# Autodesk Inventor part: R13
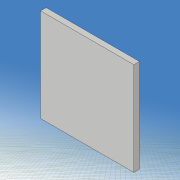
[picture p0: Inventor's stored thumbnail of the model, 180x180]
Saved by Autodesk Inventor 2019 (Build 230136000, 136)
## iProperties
Created: 2021-05
Part Number: R13
Material: 一般
Document SubType Name: Modeling
Designer: kikut
Density: 1 g/cm^3
Appearance: 既定
Mass: 0.06 g
Surface Area: 2.24 cm^2
Volume: 0.06 cm^3
Author: kikut
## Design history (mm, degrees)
sketch "スケッチ1"
  geometry: L1 (80, 60)-(-80, 60); L2 (-80, 60)-(-80, -60); L3 (-80, -60)-(80, -60); L4 (80, -60)-(80, 60); L5 (80, 60)-(-80, -60); L6 (-80, 60)-(80, -60); 1 further point
  constraints: 12 end point, 2 midpoint, 2 parallel, 1 horizontal, 1 perpendicular
  dimensions: "d0" = 160 distance of L2.end L3.end; "d1" = 120 distance of L1.end L2.end
extrude "押し出し1" new body sketch "スケッチ1" stored distance "d2" = 0.6; taper "d3" = 0 deg
sketch "スケッチ2"
  geometry: L1 (-140, 0)-(140, 0) reference; L2 (0, -54)-(20, -30); L3 (0, 54)-(20, 30); L4 (0, -3)-(6.514, -3); L5 (6.514, -3)-(16, -6); L6 (16, -6)-(24, -3); L7 (24, -3)-(33.716, -3); L8 (0, 3)-(6.514, 3); L9 (6.514, 3)-(16, 6); L10 (16, 6)-(24, 3); L11 (24, 3)-(33.716, 3); L12 (0, -98)-(0, 98) reference; L13 (-100, -70)-(100, -70); L14 (100, -70)-(100, 70); L15 (100, 70)-(-100, 70); L16 (-100, 70)-(-100, -70); L17 (-100, -70)-(100, 70); L18 (100, -70)-(-100, 70); A1 r 60 centre (54.312, 28.5) between (0, 54) and (0, 3); A2 r 60 centre (54.312, -28.5) between (0, -3) and (0, -54); A3 r 18.111 centre (18, -12) between (20, -30) and (33.716, -3); A4 r 18.111 centre (18, 12) between (33.716, 3) and (20, 30); 1 further point
  constraints: 32 end point, 8 point on circle, 8 symmetric about line, 4 centre point, 3 horizontal, 2 collinear, 2 midpoint, 2 parallel, 1 perpendicular
  dimensions: "d5" = 60 radius of A1; "d6" = 6 distance of L8.start L4.start; "d7" = 108 distance of L3.start L2.start; "d8" = 0 horizontal distance of L3.start L8.start; "d9" = 60 distance of L3.end L2.end; "d10" = 0 horizontal distance of point (0, 0) L3.start; "d11" = 20 horizontal distance of L3.start L3.end; "d12" = 24 distance of A4.centre A3.centre; "d13" = 6 distance of L11.end L7.end; "d14" = 12 distance of L9.end L5.end; "d15" = 16 distance from line of L12 L5.end; "d16" = 24 distance from line of L6.end L12; "d17" = 200 distance of L14.end L15.end; "d18" = 140 distance of L15.end L13.start; "d30" = 18 distance from line of L12 A4.centre
extrude "押し出し2" cut sketch "スケッチ2" stored distance "d19" = 10; taper "d20" = 0 deg
sketch "スケッチ3"
  geometry: L1 (49.705, -17.97)-(33.948, -15.191); L2 (33.948, -15.191)-(34.295, -13.222); L3 (34.295, -13.222)-(50.052, -16); L4 (50.052, -16)-(49.705, -17.97); L5 (49.705, -17.97)-(34.295, -13.222); L6 (33.948, -15.191)-(50.052, -16); L7 (50.052, 16)-(34.295, 13.222); L8 (34.295, 13.222)-(33.948, 15.191); L9 (33.948, 15.191)-(49.705, 17.97); L10 (49.705, 17.97)-(50.052, 16); L11 (50.052, 16)-(33.948, 15.191); L12 (34.295, 13.222)-(49.705, 17.97); L13 (-112, 0)-(112, 0) reference; L14 (0, -84)-(0, 84) reference; 3 further points
  constraints: 24 end point, 4 midpoint, 4 parallel, 2 perpendicular, 2 symmetric about line
  dimensions: "d21" = 2 distance of L3.end L1.start; "d22" = 2 distance of L9.end L7.start; "d23" = 16 distance of L8.end L9.end; "d24" = 42 distance from line of L14 point (42, 15.596); "d26" = 10 deg angle of L7 L13; "d62" = 16 distance from line of L3.end L13
extrude "押し出し3" join sketch "スケッチ3" distance "d27" = 0.6; taper "d28" = 0 deg
fillet "フィレット1" dims "d31" = 2
fillet "フィレット2" dims "d32" = 1
sketch "スケッチ6"
  geometry: L1 (-20, 60)-(80, 60); L2 (80, 60)-(80, -60); L3 (80, -60)-(-20, -60); L4 (-20, -60)-(-20, 60); L5 (-46.168, 0)-(93.832, 0) reference; L6 (0, -84)-(0, 84) reference; L7 (0, 30)-(10, 30); L8 (10, 30)-(10, 40); L9 (10, 40)-(0, 40); L10 (0, 40)-(0, 30); 1 further point
  constraints: 16 end point, 4 parallel, 2 horizontal, 2 perpendicular, 1 other
  dimensions: "d63" = 120 distance of L3.end L1.start; "d64" = 100 distance of L1.start L1.end; "d65" = 20 distance between parallel lines of L6 L4; "d66" = 10 distance of L8.end L9.end; "d73" = 10 distance of L9.end L7.start; "d74" = 30 distance between parallel lines of L7 L5; "d75" = 20 distance between parallel lines of L10 L4
extrude "押し出し4" cut sketch "スケッチ6" stored distance "d70" = 10; taper "d71" = 0 deg
node "ソリッド1"
